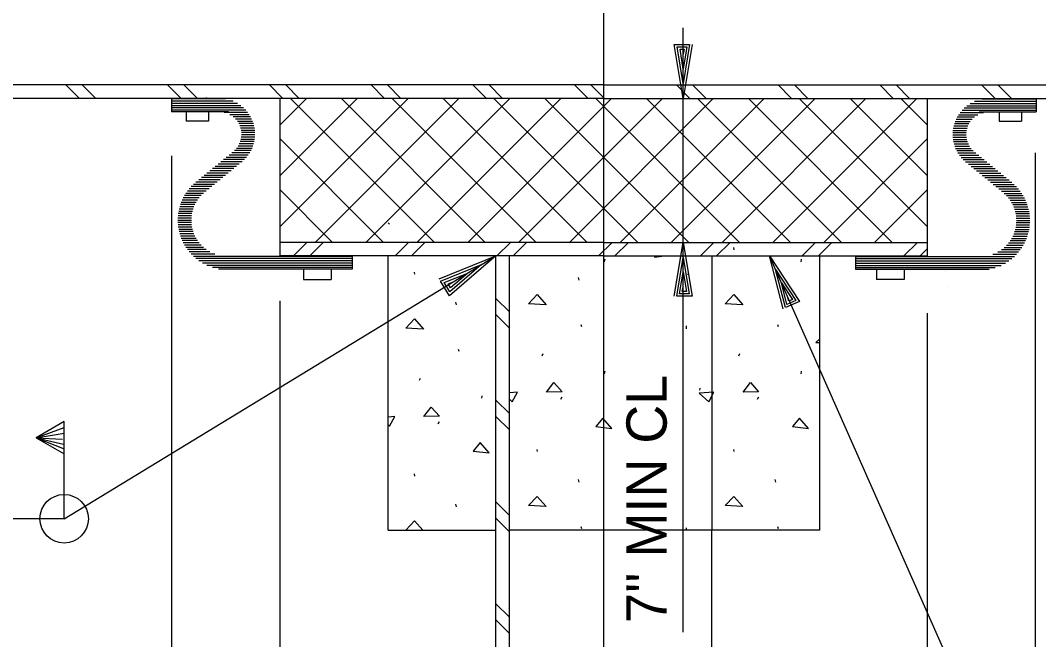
# Model space of a CAD drawing. Extents: x 22411.4 to 22495.4, y 22369.6 to 22415.
# Drawn here: x 22414.588 to 22419.306, y 22389.941 to 22392.809 of the extents above; entities that cross this region are included whole.
import ezdxf

# ---------------------------------------------------------------- set-up
doc = ezdxf.new("R2010")
doc.units = 0
for name, color, linetype in [('Level 1', 7, 'Continuous'), ('Level 10', 7, 'Continuous'), ('Level 2', 7, 'Continuous'), ('Level 4', 7, 'Continuous'), ('Level 7', 7, 'Continuous'), ('Level 8', 7, 'Continuous')]:
    doc.layers.add(name, color=color, linetype=linetype)

msp = doc.modelspace()

# ---------------------------------------------------------------- linework, layer by layer
at = {"layer": 'Level 1'}
for p, q in [((22417.2912, 22389.3264), (22417.2912, 22398.4141)), ((22417.6587, 22392.4475), (22417.6587, 22392.7748)), ((22417.6587, 22392.5168), (22417.6587, 22392.5168)), ((22417.6587, 22391.7808), (22417.6587, 22392.4475)), ((22417.6587, 22392.4475), (22417.6587, 22392.4475)), ((22415.3559, 22392.3852), (22415.3559, 22392.3422)), ((22415.4596, 22392.3852), (22415.4596, 22392.3422)), ((22419.1228, 22392.3852), (22419.1228, 22392.3422)), ((22419.2264, 22392.3852), (22419.2264, 22392.3422)), ((22415.4596, 22392.3422), (22415.3559, 22392.3422)), ((22419.1228, 22392.3422), (22419.2264, 22392.3422)), ((22415.2872, 22392.1809), (22415.2872, 22389.3882)), ((22419.2894, 22392.1948), (22419.2894, 22389.3573)), ((22417.917, 22392.0724), (22417.917, 22392.0724)), ((22417.6587, 22391.7808), (22417.6587, 22391.7808)), ((22417.6587, 22389.9752), (22417.6587, 22391.7808)), ((22416.7912, 22391.7183), (22416.7912, 22391.7183)), ((22417.2947, 22391.6905), (22417.2965, 22391.7026)), ((22417.6587, 22391.7115), (22417.6587, 22391.7115)), ((22417.8871, 22391.7183), (22417.8871, 22391.7183)), ((22415.9, 22391.6566), (22415.9, 22391.609)), ((22416.0274, 22391.6566), (22416.0274, 22391.609)), ((22418.555, 22391.6566), (22418.555, 22391.609)), ((22418.6824, 22391.6566), (22418.6824, 22391.609)), ((22415.9, 22391.609), (22416.0274, 22391.609)), ((22418.6824, 22391.609), (22418.555, 22391.609)), ((22418.8754, 22391.6464), (22418.8754, 22391.6464)), ((22418.8832, 22391.5775), (22418.8832, 22391.5775)), ((22415.7894, 22391.5095), (22415.7894, 22389.3288)), ((22418.7894, 22391.4528), (22418.7894, 22389.3573)), ((22416.6212, 22391.276), (22416.6177, 22391.285)), ((22417.9165, 22391.256), (22417.9211, 22391.2657)), ((22417.2947, 22391.172), (22417.2965, 22391.1841)), ((22416.4371, 22391.1425), (22416.4417, 22391.1523)), ((22418.0026, 22391.0543), (22418.0088, 22391.0647)), ((22416.5231, 22390.9408), (22416.5294, 22390.9512)), ((22418.1007, 22390.4543), (22418.0972, 22390.4632))]:
    msp.add_line(p, q, dxfattribs=at)
for points in [[(22417.7, 22392.6968), (22417.6587, 22392.4475), (22417.6174, 22392.6968), (22417.688, 22392.6968), (22417.6587, 22392.5168), (22417.6307, 22392.6861), (22417.676, 22392.6861), (22417.6587, 22392.5835), (22417.644, 22392.6755), (22417.6627, 22392.6755), (22417.6587, 22392.6528)], [(22416.2912, 22391.8709), (22416.2983, 22391.8646)], [(22417.6174, 22391.5315), (22417.6587, 22391.7808), (22417.7, 22391.5315), (22417.6294, 22391.5315), (22417.6587, 22391.7115), (22417.6867, 22391.5421), (22417.6414, 22391.5421), (22417.6587, 22391.6448), (22417.6734, 22391.5528), (22417.6547, 22391.5528), (22417.6587, 22391.5755)], [(22417.5265, 22391.7124), (22417.5726, 22391.7183)], [(22417.5279, 22391.7183), (22417.5265, 22391.7124)], [(22418.2912, 22391.3337), (22418.2734, 22391.3164)], [(22418.2734, 22391.3164), (22418.2912, 22391.3178)], [(22416.8537, 22391.0545), (22416.8667, 22391.0428)], [(22416.2912, 22390.9357), (22416.2983, 22390.9294)], [(22416.3803, 22390.4475), (22416.3739, 22390.4479)], [(22417.6747, 22390.4475), (22417.6747, 22390.4582)]]:
    msp.add_lwpolyline(points, dxfattribs=at)
at = {"layer": 'Level 10'}
for p, q in [((22414.7905, 22390.5008), (22416.7912, 22391.7183)), ((22416.7912, 22391.7183), (22416.7912, 22391.7183)), ((22416.7245, 22391.6777), (22416.7245, 22391.6777)), ((22414.7905, 22390.9508), (22414.6604, 22390.8758)), ((22414.7905, 22390.5008), (22414.7905, 22390.9508)), ((22414.6604, 22390.8758), (22414.7905, 22390.9227)), ((22414.6604, 22390.8758), (22414.7905, 22390.8972)), ((22414.6604, 22390.8758), (22414.7902, 22390.8008)), ((22414.6604, 22390.8758), (22414.7834, 22390.8693)), ((22414.6604, 22390.8758), (22414.7879, 22390.8462)), ((22414.6604, 22390.8758), (22414.7905, 22390.8252)), ((22414.7905, 22390.5008), (22413.29, 22390.5008))]:
    msp.add_line(p, q, dxfattribs=at)
msp.add_lwpolyline([(22416.5274, 22391.6122), (22416.7912, 22391.7183), (22416.5757, 22391.5327), (22416.5344, 22391.6007), (22416.7245, 22391.6777), (22416.5782, 22391.5518), (22416.5517, 22391.5954), (22416.6605, 22391.6388), (22416.5806, 22391.5708), (22416.5697, 22391.5888), (22416.5938, 22391.5982)], dxfattribs=at)
msp.add_circle((22414.7906, 22390.5008), 0.1125, dxfattribs=at)
at = {"layer": 'Level 2'}
for p, q in [((22417.2912, 22392.51), (22412.0509, 22392.51)), ((22417.2912, 22392.51), (22422.5315, 22392.51)), ((22417.2912, 22392.4475), (22412.0877, 22392.4475)), ((22415.2877, 22392.4475), (22415.2877, 22392.3852)), ((22415.4483, 22392.4518), (22415.4486, 22392.4478)), ((22415.7912, 22391.7183), (22415.7912, 22392.4475)), ((22417.2912, 22392.4475), (22422.4946, 22392.4475)), ((22418.7912, 22391.7183), (22418.7912, 22392.4475)), ((22419.2947, 22392.4475), (22419.2947, 22392.3852)), ((22415.5523, 22392.3852), (22415.2877, 22392.3852)), ((22419.0301, 22392.3852), (22419.2947, 22392.3852)), ((22417.2912, 22391.7808), (22415.7912, 22391.7808)), ((22417.2912, 22391.7808), (22418.7912, 22391.7808)), ((22417.2912, 22391.7183), (22415.7912, 22391.7183)), ((22416.1257, 22391.7183), (22416.1257, 22391.6566)), ((22416.7912, 22388.5454), (22416.7912, 22391.7183)), ((22416.8537, 22388.5454), (22416.8537, 22391.7183)), ((22417.2912, 22391.7183), (22418.7912, 22391.7183)), ((22417.7912, 22391.7183), (22417.7912, 22390.4475)), ((22418.4567, 22391.7183), (22418.4567, 22391.6566)), ((22416.1257, 22391.6566), (22415.5063, 22391.6566)), ((22418.4567, 22391.6566), (22419.0761, 22391.6566)), ((22417.7912, 22388.5454), (22417.7912, 22390.4475))]:
    msp.add_line(p, q, dxfattribs=at)
for points in [[(22415.5385, 22392.4453), (22415.2912, 22392.4453)], [(22415.5731, 22392.4348), (22415.2912, 22392.4348)], [(22415.5936, 22392.4244), (22415.2912, 22392.4244)], [(22415.609, 22392.414), (22415.2912, 22392.414)], [(22418.9734, 22392.414), (22419.2912, 22392.414)], [(22418.9887, 22392.4244), (22419.2912, 22392.4244)], [(22419.0092, 22392.4348), (22419.2912, 22392.4348)], [(22419.0438, 22392.4453), (22419.2912, 22392.4453)], [(22415.6214, 22392.4036), (22415.2912, 22392.4036)], [(22415.6316, 22392.3932), (22415.2912, 22392.3932)], [(22415.6403, 22392.3828), (22415.5321, 22392.3828)], [(22415.6477, 22392.3723), (22415.5589, 22392.3723)], [(22415.6539, 22392.3619), (22415.5741, 22392.3619)], [(22418.9284, 22392.3619), (22419.0082, 22392.3619)], [(22418.9347, 22392.3723), (22419.0235, 22392.3723)], [(22418.942, 22392.3828), (22419.0502, 22392.3828)], [(22418.9507, 22392.3932), (22419.2912, 22392.3932)], [(22418.961, 22392.4036), (22419.2912, 22392.4036)], [(22415.6592, 22392.3515), (22415.5851, 22392.3515)], [(22415.6636, 22392.3411), (22415.5934, 22392.3411)], [(22415.6672, 22392.3307), (22415.5998, 22392.3307)], [(22415.6701, 22392.3203), (22415.6047, 22392.3203)], [(22418.9123, 22392.3203), (22418.9777, 22392.3203)], [(22418.9151, 22392.3307), (22418.9825, 22392.3307)], [(22418.9187, 22392.3411), (22418.9889, 22392.3411)], [(22418.9232, 22392.3515), (22418.9973, 22392.3515)], [(22415.6722, 22392.3098), (22415.6082, 22392.3098)], [(22415.6737, 22392.2994), (22415.6106, 22392.2994)], [(22415.6741, 22392.2682), (22415.6113, 22392.2682)], [(22415.6745, 22392.289), (22415.6119, 22392.289)], [(22415.6747, 22392.2786), (22415.6122, 22392.2786)], [(22418.9077, 22392.2786), (22418.9702, 22392.2786)], [(22418.9079, 22392.289), (22418.9704, 22392.289)], [(22418.9082, 22392.2682), (22418.971, 22392.2682)], [(22418.9087, 22392.2994), (22418.9717, 22392.2994)], [(22418.9101, 22392.3098), (22418.9741, 22392.3098)], [(22415.6654, 22392.2265), (22415.5965, 22392.2265)], [(22415.6686, 22392.2369), (22415.6022, 22392.2369)], [(22415.6712, 22392.2473), (22415.6065, 22392.2473)], [(22415.673, 22392.2578), (22415.6095, 22392.2578)], [(22418.9094, 22392.2578), (22418.9729, 22392.2578)], [(22418.9112, 22392.2473), (22418.9759, 22392.2473)], [(22418.9138, 22392.2369), (22418.9802, 22392.2369)], [(22418.917, 22392.2265), (22418.9858, 22392.2265)], [(22415.6358, 22392.1744), (22415.5417, 22392.1744)], [(22415.6438, 22392.1848), (22415.5544, 22392.1848)], [(22415.6507, 22392.1953), (22415.5672, 22392.1953)], [(22415.6565, 22392.2057), (22415.5795, 22392.2057)], [(22415.6613, 22392.2161), (22415.5892, 22392.2161)], [(22418.921, 22392.2161), (22418.9932, 22392.2161)], [(22418.9259, 22392.2057), (22419.0028, 22392.2057)], [(22418.9317, 22392.1953), (22419.0152, 22392.1953)], [(22418.9385, 22392.1848), (22419.0279, 22392.1848)], [(22418.9466, 22392.1744), (22419.0407, 22392.1744)], [(22415.5895, 22392.1328), (22415.4906, 22392.1328)], [(22415.6022, 22392.1432), (22415.5034, 22392.1432)], [(22415.615, 22392.1536), (22415.5161, 22392.1536)], [(22415.6263, 22392.164), (22415.5289, 22392.164)], [(22418.9561, 22392.164), (22419.0535, 22392.164)], [(22418.9674, 22392.1536), (22419.0662, 22392.1536)], [(22418.9801, 22392.1432), (22419.079, 22392.1432)], [(22418.9929, 22392.1328), (22419.0918, 22392.1328)], [(22415.5256, 22392.0807), (22415.4268, 22392.0807)], [(22415.5384, 22392.0911), (22415.4395, 22392.0911)], [(22415.5512, 22392.1015), (22415.4523, 22392.1015)], [(22415.5639, 22392.1119), (22415.4651, 22392.1119)], [(22415.5767, 22392.1223), (22415.4778, 22392.1223)], [(22419.0057, 22392.1223), (22419.1045, 22392.1223)], [(22419.0184, 22392.1119), (22419.1173, 22392.1119)], [(22419.0312, 22392.1015), (22419.1301, 22392.1015)], [(22419.044, 22392.0911), (22419.1428, 22392.0911)], [(22419.0567, 22392.0807), (22419.1556, 22392.0807)], [(22415.4618, 22392.0286), (22415.3699, 22392.0286)], [(22415.4746, 22392.039), (22415.379, 22392.039)], [(22415.4873, 22392.0494), (22415.3894, 22392.0494)], [(22415.5001, 22392.0598), (22415.4013, 22392.0598)], [(22415.5129, 22392.0703), (22415.414, 22392.0703)], [(22419.0695, 22392.0703), (22419.1684, 22392.0703)], [(22419.0823, 22392.0598), (22419.1811, 22392.0598)], [(22419.095, 22392.0494), (22419.193, 22392.0494)], [(22419.1078, 22392.039), (22419.2033, 22392.039)], [(22419.1206, 22392.0286), (22419.2125, 22392.0286)], [(22415.4166, 22391.9869), (22415.3425, 22391.9869)], [(22415.4256, 22391.9973), (22415.3482, 22391.9973)], [(22415.4365, 22392.0078), (22415.3546, 22392.0078)], [(22415.449, 22392.0182), (22415.3618, 22392.0182)], [(22419.1333, 22392.0182), (22419.2206, 22392.0182)], [(22419.1459, 22392.0078), (22419.2278, 22392.0078)], [(22419.1567, 22391.9973), (22419.2342, 22391.9973)], [(22419.1658, 22391.9869), (22419.2399, 22391.9869)], [(22415.3883, 22391.9348), (22415.3234, 22391.9348)], [(22415.3921, 22391.9453), (22415.3261, 22391.9453)], [(22415.3968, 22391.9557), (22415.3294, 22391.9557)], [(22415.4023, 22391.9661), (22415.3331, 22391.9661)], [(22415.4088, 22391.9765), (22415.3375, 22391.9765)], [(22419.1735, 22391.9765), (22419.2448, 22391.9765)], [(22419.1801, 22391.9661), (22419.2492, 22391.9661)], [(22419.1856, 22391.9557), (22419.253, 22391.9557)], [(22419.1902, 22391.9453), (22419.2562, 22391.9453)], [(22419.1941, 22391.9348), (22419.2589, 22391.9348)], [(22415.3803, 22391.8932), (22415.3177, 22391.8932)], [(22415.3812, 22391.9036), (22415.3184, 22391.9036)], [(22415.3829, 22391.914), (22415.3196, 22391.914)], [(22415.3852, 22391.9244), (22415.3213, 22391.9244)], [(22419.1971, 22391.9244), (22419.2611, 22391.9244)], [(22419.1995, 22391.914), (22419.2628, 22391.914)], [(22419.2011, 22391.9036), (22419.264, 22391.9036)], [(22419.2021, 22391.8932), (22419.2647, 22391.8932)], [(22415.3799, 22391.8828), (22415.3174, 22391.8828)], [(22415.3802, 22391.8723), (22415.3177, 22391.8723)], [(22415.3812, 22391.8619), (22415.3184, 22391.8619)], [(22415.3829, 22391.8515), (22415.3195, 22391.8515)], [(22415.3852, 22391.8411), (22415.3212, 22391.8411)], [(22419.1972, 22391.8411), (22419.2611, 22391.8411)], [(22419.1995, 22391.8515), (22419.2628, 22391.8515)], [(22419.2012, 22391.8619), (22419.264, 22391.8619)], [(22419.2021, 22391.8723), (22419.2647, 22391.8723)], [(22419.2024, 22391.8828), (22419.2649, 22391.8828)], [(22415.3882, 22391.8307), (22415.3234, 22391.8307)], [(22415.392, 22391.8203), (22415.3261, 22391.8203)], [(22415.3967, 22391.8098), (22415.3293, 22391.8098)], [(22415.4022, 22391.7994), (22415.3331, 22391.7994)], [(22419.1802, 22391.7994), (22419.2493, 22391.7994)], [(22419.1857, 22391.8098), (22419.2531, 22391.8098)], [(22419.1903, 22391.8203), (22419.2563, 22391.8203)], [(22419.1941, 22391.8307), (22419.259, 22391.8307)], [(22415.4087, 22391.789), (22415.3374, 22391.789)], [(22415.4164, 22391.7786), (22415.3424, 22391.7786)], [(22415.4255, 22391.7682), (22415.3481, 22391.7682)], [(22415.4363, 22391.7578), (22415.3545, 22391.7578)], [(22415.4493, 22391.7473), (22415.3617, 22391.7473)], [(22419.1331, 22391.7473), (22419.2207, 22391.7473)], [(22419.1461, 22391.7578), (22419.2279, 22391.7578)], [(22419.1569, 22391.7682), (22419.2343, 22391.7682)], [(22419.166, 22391.7786), (22419.24, 22391.7786)], [(22419.1736, 22391.789), (22419.2449, 22391.789)], [(22415.4658, 22391.7369), (22415.3697, 22391.7369)], [(22415.4884, 22391.7265), (22415.3789, 22391.7265)], [(22416.1245, 22391.7161), (22415.3892, 22391.7161)], [(22416.1245, 22391.7057), (22415.401, 22391.7057)], [(22419.4806, 22389.0593), (22419.2355, 22389.0593), (22418.0589, 22391.7183)], [(22418.122, 22391.4736), (22418.0589, 22391.7183), (22418.1976, 22391.507), (22418.1329, 22391.4784), (22418.0869, 22391.6549), (22418.181, 22391.5114), (22418.1396, 22391.493), (22418.1139, 22391.5939), (22418.1645, 22391.5157), (22418.1475, 22391.5082), (22418.142, 22391.5305)], [(22418.4578, 22391.7161), (22419.1932, 22391.7161)], [(22418.4578, 22391.7057), (22419.1813, 22391.7057)], [(22419.094, 22391.7265), (22419.2035, 22391.7265)], [(22419.1166, 22391.7369), (22419.2126, 22391.7369)], [(22416.1245, 22391.6953), (22415.4147, 22391.6953)], [(22416.1245, 22391.6848), (22415.4309, 22391.6848)], [(22416.1245, 22391.6744), (22415.4509, 22391.6744)], [(22416.1245, 22391.664), (22415.478, 22391.664)], [(22418.4578, 22391.6953), (22419.1677, 22391.6953)], [(22418.4578, 22391.6848), (22419.1514, 22391.6848)], [(22418.4578, 22391.6744), (22419.1314, 22391.6744)], [(22418.4578, 22391.664), (22419.1043, 22391.664)]]:
    msp.add_lwpolyline(points, dxfattribs=at)
at = {"layer": 'Level 7'}
for p, q in [((22416.2912, 22390.4475), (22416.2912, 22391.7183)), ((22418.2912, 22390.4475), (22418.2912, 22391.7183)), ((22416.2912, 22390.4475), (22416.7912, 22390.4475)), ((22418.2912, 22390.4475), (22416.8537, 22390.4475))]:
    msp.add_line(p, q, dxfattribs=at)
at = {"layer": 'Level 8'}
for p, q in [((22417.8942, 22391.7468), (22417.8934, 22391.757)), ((22418.0589, 22391.7183), (22418.0589, 22391.7183)), ((22418.2057, 22391.6905), (22418.2076, 22391.7026)), ((22418.0869, 22391.6549), (22418.0869, 22391.6549)), ((22416.4148, 22391.6333), (22416.4139, 22391.6435)), ((22417.1772, 22391.6051), (22417.1736, 22391.6176)), ((22417.6824, 22391.6299), (22417.684, 22391.6393)), ((22418.0882, 22391.6051), (22418.0847, 22391.6176)), ((22416.6087, 22391.4917), (22416.6052, 22391.5042)), ((22417.1897, 22391.3895), (22417.1861, 22391.3985)), ((22417.6747, 22391.381), (22417.6747, 22391.3935)), ((22418.1007, 22391.3895), (22418.0972, 22391.3985)), ((22417.0055, 22391.256), (22417.0101, 22391.2657)), ((22418.2057, 22391.172), (22418.2076, 22391.1841)), ((22417.7365, 22391.096), (22417.7374, 22391.1051)), ((22416.7262, 22391.0585), (22416.7281, 22391.0706)), ((22417.0915, 22391.0543), (22417.0978, 22391.0647)), ((22416.9832, 22390.8116), (22416.9824, 22390.8218)), ((22417.8942, 22390.8116), (22417.8934, 22390.8218)), ((22416.4148, 22390.6981), (22416.4139, 22390.7083)), ((22417.1772, 22390.6699), (22417.1736, 22390.6824)), ((22418.0882, 22390.6699), (22418.0847, 22390.6824)), ((22416.6087, 22390.5564), (22416.6052, 22390.5689)), ((22417.424, 22390.4726), (22417.424, 22390.4843)), ((22417.1897, 22390.4543), (22417.1861, 22390.4632))]:
    msp.add_line(p, q, dxfattribs=at)
for points in [[(22414.8612, 22392.4474), (22414.7987, 22392.51)], [(22414.9366, 22392.4475), (22414.8741, 22392.51)], [(22415.3326, 22392.4475), (22415.2701, 22392.51)], [(22415.4081, 22392.4474), (22415.3455, 22392.51)], [(22415.804, 22392.4475), (22415.7415, 22392.51)], [(22415.8795, 22392.4475), (22415.817, 22392.51)], [(22416.2754, 22392.4474), (22416.2129, 22392.51)], [(22416.3509, 22392.4475), (22416.2884, 22392.51)], [(22416.7468, 22392.4475), (22416.6843, 22392.51)], [(22416.8223, 22392.4475), (22416.7598, 22392.51)], [(22417.2182, 22392.4475), (22417.1557, 22392.51)], [(22417.2937, 22392.4475), (22417.2312, 22392.51)], [(22417.6897, 22392.4475), (22417.6271, 22392.51)], [(22417.7651, 22392.4475), (22417.7026, 22392.51)], [(22418.161, 22392.4475), (22418.0985, 22392.51)], [(22418.2365, 22392.4475), (22418.174, 22392.51)], [(22418.6324, 22392.4475), (22418.57, 22392.51)], [(22418.7079, 22392.4475), (22418.6454, 22392.51)], [(22419.1039, 22392.4475), (22419.0413, 22392.51)], [(22419.1793, 22392.4475), (22419.1168, 22392.51)], [(22415.7912, 22391.8545), (22416.3842, 22392.4475)], [(22415.7912, 22392.0902), (22416.1485, 22392.4475)], [(22415.7912, 22392.3259), (22415.9128, 22392.4475)], [(22416.506, 22391.7808), (22415.8393, 22392.4475)], [(22415.9532, 22391.7808), (22416.6199, 22392.4475)], [(22416.7417, 22391.7808), (22416.075, 22392.4475)], [(22416.1889, 22391.7808), (22416.8556, 22392.4475)], [(22416.9774, 22391.7808), (22416.3107, 22392.4475)], [(22416.4246, 22391.7808), (22417.0913, 22392.4475)], [(22417.2131, 22391.7808), (22416.5464, 22392.4475)], [(22416.6603, 22391.7808), (22417.327, 22392.4475)], [(22417.4488, 22391.7808), (22416.7821, 22392.4475)], [(22416.896, 22391.7808), (22417.5627, 22392.4475)], [(22417.6845, 22391.7808), (22417.0178, 22392.4475)], [(22417.1317, 22391.7808), (22417.7984, 22392.4475)], [(22417.9202, 22391.7808), (22417.2535, 22392.4475)], [(22417.3674, 22391.7808), (22418.0341, 22392.4475)], [(22418.1559, 22391.7808), (22417.4892, 22392.4475)], [(22417.6031, 22391.7808), (22418.2698, 22392.4475)], [(22418.3916, 22391.7808), (22417.7249, 22392.4475)], [(22417.8388, 22391.7808), (22418.5055, 22392.4475)], [(22418.6273, 22391.7808), (22417.9606, 22392.4475)], [(22418.0745, 22391.7808), (22418.7412, 22392.4475)], [(22418.7912, 22391.8526), (22418.1963, 22392.4475)], [(22418.7912, 22392.0883), (22418.432, 22392.4475)], [(22418.7912, 22392.324), (22418.6677, 22392.4475)], [(22416.2702, 22391.7808), (22415.7912, 22392.2599)], [(22418.3102, 22391.7808), (22418.7912, 22392.2618)], [(22416.0345, 22391.7808), (22415.7912, 22392.0242)], [(22418.5459, 22391.7808), (22418.7912, 22392.026)], [(22415.8527, 22391.7183), (22415.9152, 22391.7808)], [(22415.9282, 22391.7183), (22415.9907, 22391.7808)], [(22416.3241, 22391.7183), (22416.3866, 22391.7808)], [(22416.3996, 22391.7183), (22416.4621, 22391.7808)], [(22416.7955, 22391.7183), (22416.858, 22391.7808)], [(22416.871, 22391.7183), (22416.9335, 22391.7808)], [(22417.2669, 22391.7183), (22417.3294, 22391.7808)], [(22417.3424, 22391.7183), (22417.4049, 22391.7808)], [(22417.7383, 22391.7183), (22417.8008, 22391.7808)], [(22417.8138, 22391.7183), (22417.8763, 22391.7808)], [(22418.2098, 22391.7183), (22418.2723, 22391.7808)], [(22418.2852, 22391.7183), (22418.3477, 22391.7808)], [(22418.6812, 22391.7183), (22418.7437, 22391.7808)], [(22418.7566, 22391.7183), (22418.7912, 22391.7529)], [(22416.8537, 22391.459), (22416.7912, 22391.5215)], [(22416.8537, 22391.3835), (22416.7912, 22391.446)], [(22416.8905, 22391.0872), (22416.8537, 22391.0846)], [(22416.8667, 22391.0428), (22416.8905, 22391.0872)], [(22416.8537, 22390.9876), (22416.7912, 22391.0501)], [(22416.3221, 22390.9737), (22416.2912, 22390.9716)], [(22416.2983, 22390.9294), (22416.3221, 22390.9737)], [(22416.8537, 22390.9122), (22416.7912, 22390.9746)], [(22416.8537, 22390.5162), (22416.7912, 22390.5787)], [(22416.3739, 22390.4479), (22416.4135, 22390.4908)], [(22416.4135, 22390.4908), (22416.4522, 22390.4475)], [(22416.8537, 22390.4407), (22416.7912, 22390.5032)], [(22416.8537, 22390.0448), (22416.7912, 22390.1073)], [(22416.8537, 22389.9693), (22416.7912, 22390.0318)]]:
    msp.add_lwpolyline(points, dxfattribs=at)
for points in [[(22416.9424, 22391.4966), (22416.982, 22391.5395), (22417.0245, 22391.492)], [(22417.8534, 22391.4966), (22417.893, 22391.5395), (22417.9355, 22391.492)], [(22416.3739, 22391.3831), (22416.4135, 22391.426), (22416.456, 22391.3785)], [(22417.0261, 22391.0872), (22417.0597, 22391.1316), (22417.0974, 22391.0889)], [(22417.7334, 22391.0824), (22417.7778, 22391.0428), (22417.8015, 22391.0872)], [(22417.9372, 22391.0872), (22417.9707, 22391.1316), (22418.0084, 22391.0889)], [(22416.4577, 22390.9737), (22416.4912, 22391.0181), (22416.5289, 22390.9754)], [(22417.3278, 22390.9193), (22417.2865, 22390.9668), (22417.2534, 22390.9274)], [(22418.2388, 22390.9193), (22418.1976, 22390.9668), (22418.1645, 22390.9274)], [(22416.7594, 22390.8058), (22416.7181, 22390.8533), (22416.685, 22390.8139)], [(22416.9424, 22390.5614), (22416.982, 22390.6043), (22417.0245, 22390.5568)], [(22417.8534, 22390.5614), (22417.893, 22390.6043), (22417.9355, 22390.5568)]]:
    msp.add_lwpolyline(points, close=True, dxfattribs=at)

# ---------------------------------------------------------------- texts
at = {"layer": 'Level 4'}
msp.add_text("7'' MIN CL", height=0.18667, rotation=90, dxfattribs=at).set_placement((22417.5823, 22390.018))

doc.saveas('drawing.dxf')
